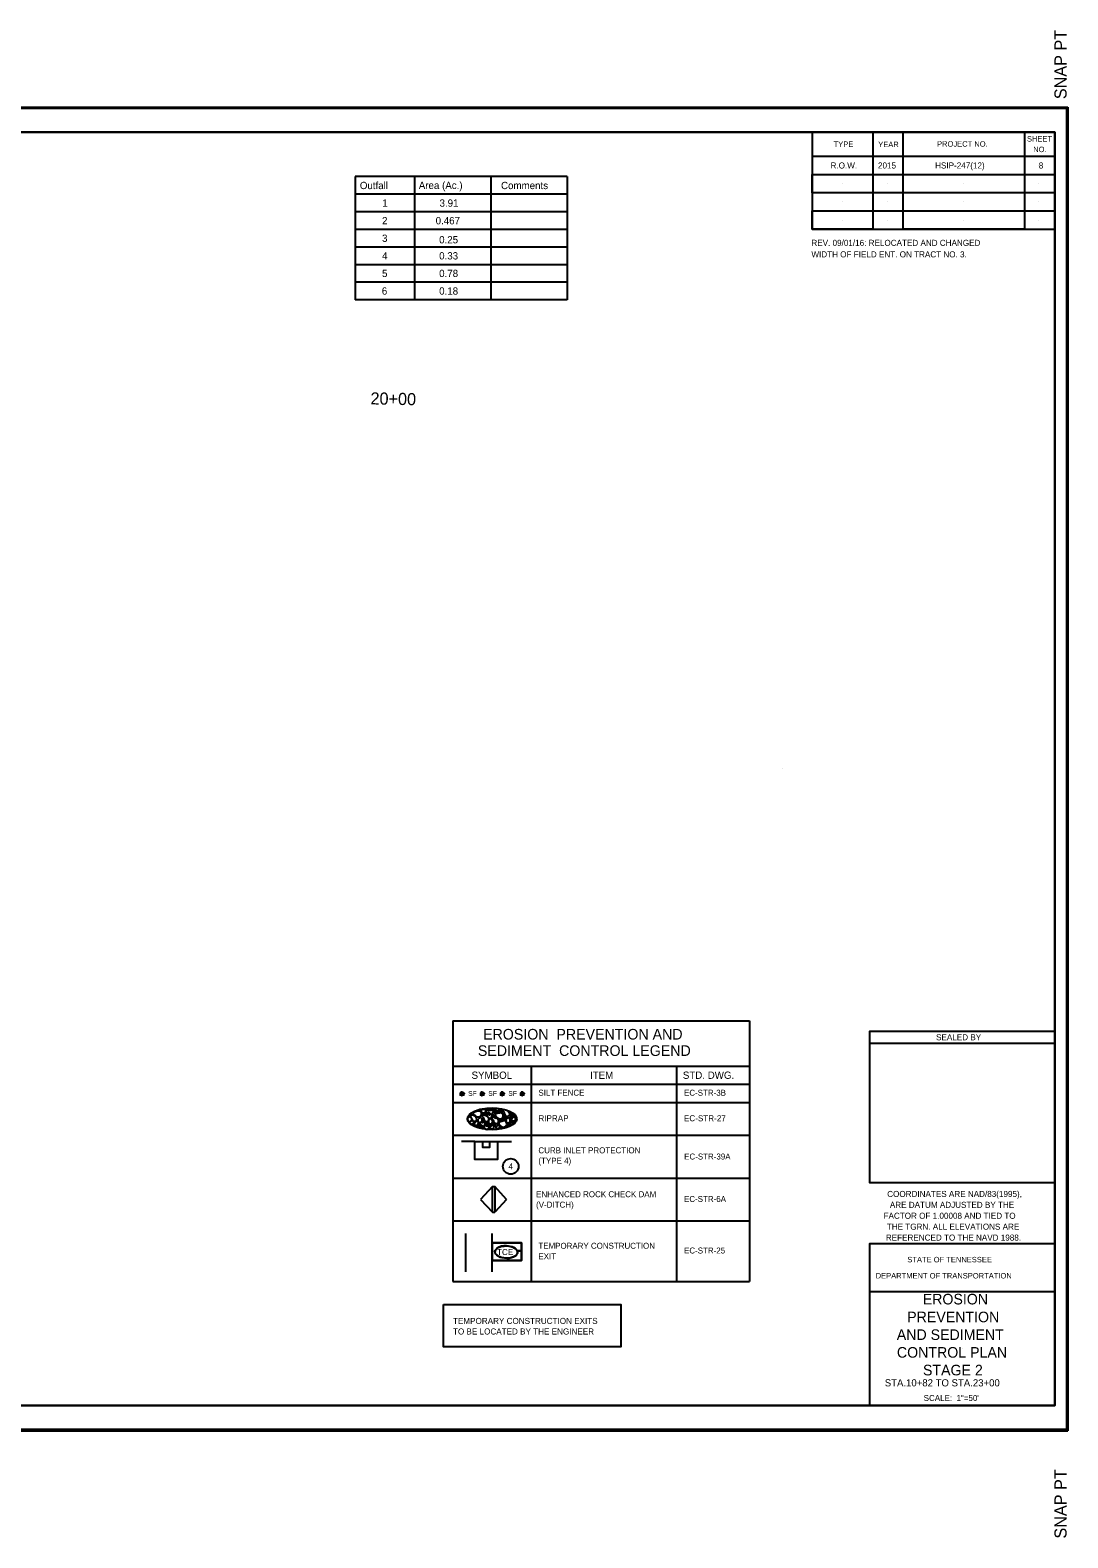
# Model space of a CAD drawing. Extents: x -200 to 1681714, y -325 to 518733.
# Drawn here: x 1680858 to 1681714, y 517490 to 518733 of the extents above; entities that cross this region are included whole.
import ezdxf

# ---------------------------------------------------------------- set-up
doc = ezdxf.new("R2010")
doc.units = 0
for name, color, linetype in [('DESIGN - CENTERLINE - Proposed Text', 7, 'Continuous'), ('DESIGN - EROSION CONTROL - Devices Text and Legends', 7, 'Continuous'), ('DESIGN - SCRATCH - User 1', 7, 'Continuous'), ('DESIGN - SHEET - Corner Text', 7, 'Continuous'), ('DESIGN - SHEET - Linework', 7, 'Continuous'), ('DESIGN - SHEET - Plot Shape', 7, 'Continuous'), ('DESIGN - TRANSPORTATION - Text', 7, 'Continuous')]:
    doc.layers.add(name, color=color, linetype=linetype)

msp = doc.modelspace()

# ---------------------------------------------------------------- linework, layer by layer
at = {"layer": 'DESIGN - EROSION CONTROL - Devices Text and Legends'}
for p, q in [((1681206.9, 517916.1), (1681206.9, 517863.9)), ((1681206.9, 517916.1), (1681451.4, 517916.1)), ((1681451.4, 517916.1), (1681451.4, 517863.9)), ((1681206.9, 517878.9), (1681451.4, 517878.9)), ((1681271.4, 517878.9), (1681271.4, 517863.9)), ((1681391.4, 517878.9), (1681391.4, 517863.9)), ((1681206.9, 517863.9), (1681451.4, 517863.9)), ((1681206.9, 517863.9), (1681206.9, 517848.8)), ((1681271.5, 517863.9), (1681271.5, 517848.8)), ((1681391.4, 517863.9), (1681391.4, 517848.8)), ((1681451.4, 517863.9), (1681451.4, 517848.8)), ((1681206.9, 517848.8), (1681206.9, 517822)), ((1681271.4, 517848.8), (1681271.4, 517822)), ((1681391.4, 517848.8), (1681391.4, 517822)), ((1681451.4, 517848.8), (1681451.4, 517822)), ((1681206.9, 517822), (1681206.9, 517786.6)), ((1681225, 517816.6), (1681214.1, 517816.6)), ((1681243.8, 517816.6), (1681255.2, 517816.6)), ((1681271.5, 517822), (1681271.5, 517786.6)), ((1681391.4, 517822), (1681391.4, 517786.6)), ((1681451.4, 517822), (1681451.4, 517786.6)), ((1681206.9, 517786.6), (1681206.9, 517751.2)), ((1681239.6, 517779.6), (1681229.8, 517769)), ((1681239.6, 517779.6), (1681241.4, 517779.6)), ((1681239.6, 517758.4), (1681239.6, 517779.6)), ((1681241.4, 517779.6), (1681241.4, 517758.4)), ((1681251.2, 517769), (1681241.4, 517779.6)), ((1681271.5, 517786.6), (1681271.5, 517751.2)), ((1681391.4, 517786.6), (1681391.4, 517751.2)), ((1681451.4, 517786.6), (1681451.4, 517751.2)), ((1681229.8, 517769), (1681239.6, 517758.4)), ((1681251.2, 517769), (1681241.4, 517758.4)), ((1681239.6, 517758.4), (1681241.4, 517758.4)), ((1681206.9, 517751.2), (1681206.9, 517701.4)), ((1681217.7, 517709.2), (1681217.7, 517741)), ((1681239.2, 517709.2), (1681239.2, 517741)), ((1681271.5, 517751.2), (1681271.5, 517701.4)), ((1681391.4, 517751.2), (1681391.4, 517701.4)), ((1681451.4, 517751.2), (1681451.4, 517701.4)), ((1681206.9, 517701.4), (1681451.4, 517701.4))]:
    msp.add_line(p, q, dxfattribs=at)
for points in [[(1681212.4, 517856.2), (1681216.4, 517856.2), (1681214.4, 517856.2), (1681214.4, 517854.3), (1681214.4, 517858.2)], [(1681213, 517857.6), (1681215.8, 517854.9), (1681214.4, 517856.2), (1681213, 517854.9), (1681215.8, 517857.6)], [(1681229, 517856.2), (1681232.9, 517856.2), (1681230.9, 517856.2), (1681230.9, 517854.3), (1681230.9, 517858.2)], [(1681229.6, 517857.6), (1681232.3, 517854.9), (1681230.9, 517856.2), (1681229.6, 517854.9), (1681232.3, 517857.6)], [(1681245.5, 517856.2), (1681249.4, 517856.2), (1681247.5, 517856.2), (1681247.5, 517854.3), (1681247.5, 517858.2)], [(1681246.1, 517857.6), (1681248.9, 517854.9), (1681247.5, 517856.2), (1681246.1, 517854.9), (1681248.9, 517857.6)], [(1681262, 517856.2), (1681266, 517856.2), (1681264, 517856.2), (1681264, 517854.3), (1681264, 517858.2)], [(1681262.6, 517857.6), (1681265.4, 517854.9), (1681264, 517856.2), (1681262.6, 517854.9), (1681265.4, 517857.6)], [(1681206.9, 517848.8), (1681451.4, 517848.8)], [(1681206.9, 517822), (1681451.4, 517822)], [(1681206.9, 517786.6), (1681451.4, 517786.6)], [(1681206.9, 517751.2), (1681451.4, 517751.2)], [(1681206.9, 517701.4), (1681451.4, 517701.4)]]:
    msp.add_lwpolyline(points, dxfattribs=at)
for points in [[(1681223.8, 517830.2), (1681227.7, 517830.2), (1681227.9, 517833.2), (1681225.4, 517832.9)], [(1681236.8, 517827.1), (1681240.7, 517827.1), (1681240.9, 517830.1), (1681238.4, 517829.8)], [(1681254.5, 517833.8), (1681258.5, 517833.8), (1681258.6, 517836.7), (1681256.1, 517836.5)], [(1681225, 517816.6), (1681243.8, 517816.6), (1681243.8, 517801.9), (1681225, 517801.9)], [(1681231.6, 517816.6), (1681237.2, 517816.6), (1681237.2, 517811.8), (1681231.6, 517811.8)], [(1681239.2, 517733.2), (1681263.6, 517733.2), (1681263.6, 517726.7), (1681260, 517726.7), (1681259.4, 517727.6), (1681258.5, 517728.4), (1681257.1, 517729.3), (1681255.7, 517729.9), (1681254.2, 517730.2), (1681252.8, 517730.5), (1681251, 517730.6), (1681249, 517730.6), (1681246.9, 517730.3), (1681244.7, 517729.6), (1681243.4, 517728.8), (1681242.2, 517727.7), (1681241.7, 517726.7), (1681241.5, 517725.7), (1681241.8, 517724.5), (1681242.5, 517723.6), (1681243.4, 517722.9), (1681244.7, 517722), (1681246, 517721.5), (1681247.4, 517721.1), (1681249.5, 517720.7), (1681249.5, 517720.7), (1681251.4, 517720.6), (1681253.2, 517720.6), (1681255.1, 517721), (1681257, 517721.6), (1681258.4, 517722.4), (1681258.7, 517722.6), (1681259.7, 517723.6), (1681260.3, 517724.8), (1681260.3, 517726), (1681260, 517726.7), (1681263.6, 517726.7), (1681263.6, 517718.5), (1681239.2, 517718.5)], [(1681239.2, 517718.5), (1681263.6, 517718.5), (1681263.6, 517733.2), (1681239.2, 517733.2)], [(1681199.2, 517682.2), (1681345.4, 517682.2), (1681345.4, 517647.4), (1681199.2, 517647.4)]]:
    msp.add_lwpolyline(points, close=True, dxfattribs=at)
msp.add_circle((1681254.6, 517796.2), 6.49, dxfattribs=at)
for centre, major_axis, ratio in [((1681239.2, 517835.4), (20.3, 0), 0.441611), ((1681250.9, 517725.6), (9.39, -0.3), 0.529481)]:
    msp.add_ellipse(centre, major_axis=major_axis, ratio=ratio, dxfattribs=at)
for points in [[(1681223.9, 517840.9), (1681223.9, 517839.5), (1681225.5, 517837.8), (1681227.1, 517836.9), (1681230.1, 517838.4), (1681229.3, 517841.9), (1681227.1, 517841.9), (1681223.9, 517840.9)], [(1681227.8, 517842.6), (1681228.5, 517841.9), (1681229.6, 517843.1), (1681227.9, 517842.6)], [(1681230.3, 517842.8), (1681231, 517840.3), (1681233.5, 517841), (1681233.5, 517843.2), (1681232, 517843.5), (1681230.3, 517842.8)], [(1681232.1, 517839.9), (1681231.4, 517839.1), (1681232.2, 517838.7), (1681232.9, 517839.5), (1681232, 517839.9)], [(1681233, 517839.1), (1681234.4, 517838), (1681234.9, 517837.7), (1681234.6, 517838.5), (1681235, 517838.8), (1681234.7, 517839.5), (1681234.3, 517839.9), (1681234.3, 517840.9), (1681234.1, 517841.3), (1681233.6, 517840.3), (1681233.1, 517839.1)], [(1681237.2, 517844.1), (1681234, 517842.8), (1681234.9, 517842.5), (1681236.9, 517842.7), (1681238.3, 517844.1), (1681237.2, 517844.1)], [(1681234.5, 517840.9), (1681234.6, 517839.5), (1681235.7, 517839.9), (1681234.9, 517840.8), (1681234.5, 517840.8)], [(1681234.9, 517838.2), (1681238.2, 517836.1), (1681239.4, 517839.3), (1681237.3, 517838.7), (1681236, 517839), (1681234.8, 517838.3)], [(1681235.6, 517841.6), (1681238.9, 517839.5), (1681240.1, 517842.7), (1681237.9, 517842.2), (1681236.6, 517842.5), (1681235.4, 517841.8)], [(1681236.4, 517840.4), (1681236.2, 517839.2), (1681237.3, 517838.8), (1681237.9, 517839.2), (1681237.1, 517840.3), (1681236.4, 517840.3)], [(1681238.8, 517844.2), (1681239, 517842.8), (1681240, 517843.2), (1681239.2, 517844.1), (1681238.8, 517844.2)], [(1681241.2, 517841.5), (1681240.6, 517840.7), (1681241.4, 517840.3), (1681242, 517841), (1681241.1, 517841.4)], [(1681240.7, 517844.1), (1681241.3, 517842), (1681241.7, 517841.2), (1681242.5, 517841.1), (1681243.6, 517841.6), (1681242.2, 517842.9), (1681240.7, 517844.1)], [(1681241.8, 517839.5), (1681242.1, 517837.9), (1681243.7, 517836.2), (1681245.3, 517835.2), (1681248.2, 517836.8), (1681247.4, 517840.2), (1681245.3, 517840.2), (1681241.6, 517839.5)], [(1681243.5, 517841.4), (1681242.5, 517840.9), (1681241.9, 517840.1), (1681242.5, 517839.9), (1681244.1, 517840.4), (1681244.7, 517840.8), (1681244, 517841.3), (1681243.6, 517841.3)], [(1681244.3, 517842.7), (1681244.2, 517841.5), (1681245.2, 517841), (1681245.9, 517841.5), (1681245, 517842.6), (1681244.3, 517842.7)], [(1681245.7, 517843.7), (1681245.8, 517842.2), (1681246.9, 517842.6), (1681246.1, 517843.5), (1681245.7, 517843.7)], [(1681246.7, 517842.1), (1681247.6, 517840.7), (1681248.4, 517840.8), (1681248.1, 517841.6), (1681246.7, 517842.1)], [(1681247.8, 517842.4), (1681249.2, 517840.3), (1681251.4, 517837.5), (1681253.4, 517838.1), (1681253.6, 517840.2), (1681251.1, 517842.4), (1681247.8, 517842.8)], [(1681254.5, 517840.8), (1681255, 517839), (1681255.4, 517838.2), (1681256.2, 517838.1), (1681257.3, 517838.6), (1681255.9, 517839.9), (1681254.5, 517841.1)], [(1681219, 517835.8), (1681219.7, 517833.3), (1681222.2, 517834), (1681222.2, 517836.2), (1681220.7, 517837.2), (1681219.3, 517836.1)], [(1681222.7, 517833.9), (1681220.7, 517832.4), (1681222.7, 517831.1), (1681224.2, 517832.4), (1681222.7, 517834)], [(1681220.7, 517838.2), (1681222.1, 517836.2), (1681224.4, 517833.4), (1681226.4, 517834), (1681226.5, 517836), (1681224, 517838.2), (1681220.7, 517838.7)], [(1681227.5, 517830), (1681227.4, 517828.9), (1681228.4, 517828.4), (1681229, 517828.8), (1681228.2, 517829.9), (1681227.5, 517830)], [(1681227.5, 517835.1), (1681228.2, 517832.6), (1681230.7, 517833.2), (1681230.7, 517835.5), (1681229.2, 517836.4), (1681227.8, 517835.4)], [(1681228.3, 517831.7), (1681228.4, 517830.2), (1681229.5, 517830.6), (1681228.7, 517831.5), (1681228.3, 517831.5)], [(1681229.1, 517831.7), (1681232.4, 517829.6), (1681233.6, 517832.8), (1681231.4, 517832.2), (1681230.1, 517832.5), (1681228.9, 517831.8)], [(1681229.3, 517830.4), (1681229.9, 517828.6), (1681230.3, 517827.8), (1681231.1, 517827.7), (1681232.1, 517828.2), (1681230.8, 517829.5), (1681229.3, 517830.7)], [(1681230.7, 517838), (1681232.1, 517835.9), (1681234.3, 517833.1), (1681236.3, 517833.7), (1681236.5, 517835.8), (1681234, 517838), (1681230.7, 517838.4)], [(1681231.7, 517835.7), (1681231, 517834.9), (1681231.8, 517834.5), (1681232.5, 517835.3), (1681231.6, 517835.7)], [(1681232.2, 517833.9), (1681231.6, 517833.2), (1681232.4, 517832.8), (1681233, 517833.5), (1681232.1, 517833.9)], [(1681232.4, 517828.9), (1681235.7, 517826.8), (1681236.9, 517830), (1681234.7, 517829.4), (1681233.4, 517829.7), (1681232.2, 517829)], [(1681234, 517832.6), (1681234.5, 517830.7), (1681234.9, 517830), (1681235.7, 517829.8), (1681236.8, 517830.4), (1681235.4, 517831.7), (1681234, 517832.9)], [(1681236.2, 517833.9), (1681236.9, 517831.4), (1681239.4, 517832.1), (1681239.4, 517834.4), (1681237.9, 517835.3), (1681236.5, 517834.2)], [(1681238.7, 517831.7), (1681238.5, 517830.5), (1681239.6, 517830), (1681240.2, 517830.4), (1681239.4, 517831.5), (1681238.7, 517831.6)], [(1681238.6, 517836.4), (1681240, 517834.4), (1681242.3, 517831.5), (1681244.3, 517832.2), (1681244.4, 517834.2), (1681241.9, 517836.4), (1681238.6, 517836.9)], [(1681240.1, 517838.7), (1681240.2, 517837.2), (1681241.3, 517837.6), (1681240.5, 517838.6), (1681240.1, 517838.6)], [(1681240.4, 517831.9), (1681240.7, 517830.2), (1681241.4, 517829.7), (1681242, 517830.3), (1681242.4, 517831), (1681241, 517831.8), (1681240.4, 517832)], [(1681241.3, 517837.7), (1681241.1, 517836.5), (1681242.2, 517836.1), (1681242.8, 517836.5), (1681242, 517837.6), (1681241.3, 517837.6)], [(1681244.2, 517830.4), (1681242.3, 517827.9), (1681244.2, 517827.5), (1681245.7, 517828.8), (1681244.1, 517830.4)], [(1681244.6, 517832.7), (1681244.9, 517831.1), (1681246.5, 517829.4), (1681248.1, 517828.5), (1681251.1, 517830), (1681250.2, 517833.5), (1681248.1, 517833.5), (1681244.6, 517832.5)], [(1681245.6, 517835.2), (1681244.9, 517834.4), (1681245.7, 517834), (1681246.4, 517834.8), (1681245.5, 517835.2)], [(1681248.7, 517835.6), (1681245.6, 517834.3), (1681246.4, 517833.9), (1681248.5, 517834.2), (1681249.8, 517835.5), (1681248.7, 517835.6)], [(1681246.3, 517828.6), (1681245.6, 517827.8), (1681246.4, 517827.4), (1681247.1, 517828.1), (1681246.2, 517828.5)], [(1681249.1, 517838), (1681249.2, 517836.6), (1681250.1, 517836.3), (1681250.6, 517837.3), (1681250.9, 517837.8), (1681250.1, 517838.1), (1681248.9, 517838.1)], [(1681250.2, 517836.4), (1681250.9, 517835.6), (1681252.1, 517836.8), (1681250.4, 517836.4)], [(1681250.7, 517834.8), (1681251.3, 517832.3), (1681253.8, 517833), (1681253.8, 517835.2), (1681252.4, 517836.2), (1681250.9, 517835.1)], [(1681251.7, 517830), (1681252.6, 517829.1), (1681252.7, 517828.9), (1681252.8, 517829.5), (1681253.2, 517829.9), (1681252.9, 517830.5), (1681252.5, 517831), (1681253.1, 517831.5), (1681252.8, 517831.9), (1681251.8, 517831.4), (1681251.7, 517830.2)], [(1681253.5, 517832.1), (1681253.6, 517830.7), (1681254.7, 517831.1), (1681253.9, 517832), (1681253.5, 517832)], [(1681254.1, 517839.1), (1681253.4, 517838.3), (1681254.3, 517837.9), (1681254.9, 517838.6), (1681254, 517839.1)], [(1681254, 517837.1), (1681254.1, 517835.8), (1681254.9, 517835.4), (1681255.5, 517836.4), (1681255.8, 517837), (1681255, 517837.3), (1681253.8, 517837.2)], [(1681254.4, 517833.7), (1681254.3, 517832.6), (1681255.3, 517832.1), (1681255.9, 517832.5), (1681255.1, 517833.6), (1681254.4, 517833.7)], [(1681256.3, 517833.4), (1681256.4, 517831.9), (1681257.5, 517832.3), (1681256.7, 517833.2), (1681256.3, 517833.2)], [(1681257.5, 517838.3), (1681256.9, 517837.5), (1681257.7, 517837.1), (1681258.3, 517837.8), (1681257.4, 517838.2)]]:
    msp.add_spline(points, degree=3, dxfattribs=at)
at = {"layer": 'DESIGN - SCRATCH - User 1'}
for p, q in [((1681528.1, 518621.5), (1681528.1, 518621.5)), ((1681565.1, 518621.5), (1681565.1, 518621.5)), ((1681627.6, 518621.5), (1681627.6, 518621.5)), ((1681690.1, 518621.5), (1681690.1, 518621.5)), ((1681528.1, 518606.5), (1681528.1, 518606.5)), ((1681565.1, 518606.5), (1681565.1, 518606.5)), ((1681627.6, 518606.5), (1681627.6, 518606.5)), ((1681690.1, 518606.5), (1681690.1, 518606.5)), ((1681528.1, 518591.5), (1681528.1, 518591.5)), ((1681565.1, 518591.5), (1681565.1, 518591.5)), ((1681627.6, 518591.5), (1681627.6, 518591.5)), ((1681690.1, 518591.5), (1681690.1, 518591.5)), ((1681528.1, 518576.5), (1681528.1, 518576.5)), ((1681565.1, 518576.5), (1681565.1, 518576.5)), ((1681627.6, 518576.5), (1681627.6, 518576.5)), ((1681690.1, 518576.5), (1681690.1, 518576.5)), ((1681478.9, 518124), (1681478.9, 518124)), ((1681626.8, 517645.8), (1681626.8, 517645.8))]:
    msp.add_line(p, q, dxfattribs=at)
at = {"layer": 'DESIGN - SHEET - Linework'}
for p, q in [((1680011.9, 518669.7), (1681713.9, 518669.7)), ((1681713.9, 518669.7), (1681713.9, 517578.3)), ((1681550.6, 517897.7), (1681703.1, 517897.7)), ((1680011.9, 517578.3), (1681713.9, 517578.3))]:
    msp.add_line(p, q, dxfattribs=at)
for points in [[(1680128.9, 518649), (1680128.9, 517599), (1681703.1, 517599), (1681703.1, 518649), (1680128.9, 518649)], [(1681503.1, 518649), (1681503.1, 518569), (1681703.1, 518569), (1681703.1, 518649), (1681678.1, 518649), (1681678.1, 518569), (1681578.1, 518569), (1681578.1, 518649), (1681553.1, 518649), (1681553.1, 518569), (1681503.1, 518569), (1681503.1, 518584), (1681703.1, 518584), (1681703.1, 518599), (1681503.1, 518599), (1681503.1, 518614), (1681703.1, 518614), (1681703.1, 518629), (1681503.1, 518629)], [(1681550.6, 517599), (1681550.6, 517732.7), (1681703.1, 517732.7), (1681703.1, 517692.7), (1681550.6, 517692.7)]]:
    msp.add_lwpolyline(points, dxfattribs=at)
msp.add_lwpolyline([(1681703.1, 517782.7), (1681550.6, 517782.7), (1681550.6, 517907.7), (1681703.1, 517907.7)], close=True, dxfattribs=at)
at = {"layer": 'DESIGN - SHEET - Plot Shape'}
for points in [[(1680012.9, 518668.7), (1681712.9, 518668.7), (1681712.9, 517579.3), (1680012.9, 517579.3)], [(1680043.8, 518649), (1681703.1, 518649), (1681703.1, 517599), (1680043.8, 517599)]]:
    msp.add_lwpolyline(points, close=True, dxfattribs=at)
at = {"layer": 'DESIGN - TRANSPORTATION - Text'}
for p, q in [((1681301, 518612.3), (1681126.2, 518612.3)), ((1681126.2, 518612.3), (1681126.2, 518510.7)), ((1681175.2, 518612.3), (1681175.2, 518510.7)), ((1681238.1, 518612.3), (1681238.1, 518510.7)), ((1681301, 518612.3), (1681301, 518510.7)), ((1681301, 518597.7), (1681126.2, 518597.8)), ((1681301, 518583.2), (1681126.2, 518583.3)), ((1681301, 518568.7), (1681126.2, 518568.8)), ((1681301, 518554.2), (1681126.2, 518554.2)), ((1681301, 518539.7), (1681126.2, 518539.7)), ((1681301, 518525.2), (1681126.2, 518525.2)), ((1681301, 518510.7), (1681126.2, 518510.7))]:
    msp.add_line(p, q, dxfattribs=at)

# ---------------------------------------------------------------- texts
at = {"layer": 'DESIGN - CENTERLINE - Proposed Text'}
msp.add_text('20+00', height=10, rotation=358.8704, dxfattribs=at).set_placement((1681138.9, 518424.5))
at = {"layer": 'DESIGN - EROSION CONTROL - Devices Text and Legends'}
for s, height, p in [('EROSION  PREVENTION AND', 8.75, (1681231.8, 517900.8)), ('SEDIMENT  CONTROL LEGEND', 8.75, (1681227.5, 517887.3)), ('SYMBOL', 6, (1681222.3, 517868.4)), ('ITEM', 6, (1681320, 517868.4)), ('STD. DWG.', 6, (1681396.5, 517868.4)), ('SF', 4, (1681219.5, 517854.3)), ('SF', 4, (1681236.1, 517854.3)), ('SF', 4, (1681252.6, 517854.3)), ('SILT FENCE', 4.92, (1681277.4, 517854.5)), ('EC-STR-3B', 4.9, (1681397.5, 517854.5)), ('RIPRAP', 5, (1681277.4, 517833.4)), ('EC-STR-27', 5, (1681397.4, 517833.4)), ('CURB INLET PROTECTION', 4.921, (1681277.4, 517807)), ('(TYPE 4)', 4.92, (1681277.4, 517798.4)), ('EC-STR-39A', 4.9, (1681397.6, 517801.9)), ('(V-DITCH)', 4.92, (1681275.5, 517762.2)), ('ENHANCED ROCK CHECK DAM ', 4.921, (1681275.5, 517770.8)), ('EC-STR-6A', 4.9, (1681397.5, 517766.9)), ('TCE', 5, (1681243.3, 517723.1)), ('TEMPORARY CONSTRUCTION', 4.9, (1681277.4, 517728.3)), ('EC-STR-25', 4.9, (1681397.5, 517724.4)), ('EXIT', 4.9, (1681277.4, 517719.6)), ('TEMPORARY CONSTRUCTION EXITS', 5, (1681207, 517666.3)), ('TO BE LOCATED BY THE ENGINEER', 5, (1681207, 517657.6))]:
    msp.add_text(s, height=height, dxfattribs=at).set_placement(p)
msp.add_text('4', height=5, rotation=359.7818, dxfattribs=at).set_placement((1681252.7, 517793.7))
at = {"layer": 'DESIGN - SHEET - Corner Text'}
for s, height, rotation, p in [('  SNAP PT', 10, 90, (1681712.9, 518668.7)), ('REV. 09/01/16: RELOCATED AND CHANGED', 5, 360, (1681502.5, 518555.2)), ('WIDTH OF FIELD ENT. ON TRACT NO. 3.', 5, 360, (1681502.5, 518545.7)), ('SEALED BY', 5, 360, (1681605.3, 517900.2)), ('SNAP PT  ', 10, 90, (1681712.9, 517489.3))]:
    msp.add_text(s, height=height, rotation=rotation, dxfattribs=at).set_placement(p)
for s, height, p in [('NO.', 4.5, (1681685.4, 518632.5)), ('R.O.W.', 5, (1681518.3, 518619)), ('2015', 5, (1681557.4, 518619)), ('HSIP-247(12)', 5, (1681604.5, 518619)), ('8', 5, (1681690, 518619)), ('COORDINATES ARE NAD/83(1995),', 5, (1681565, 517771)), ('ARE DATUM ADJUSTED BY THE', 5, (1681567.2, 517762)), ('FACTOR OF 1.00008 AND TIED TO', 5, (1681562, 517753)), ('REFERENCED TO THE NAVD 1988.', 5, (1681563.9, 517735)), ('THE TGRN. ALL ELEVATIONS ARE', 5, (1681564.7, 517744)), ('STATE OF TENNESSEE', 4.5, (1681581.6, 517717.1)), ('DEPARTMENT OF TRANSPORTATION', 4.5, (1681555.5, 517703.8)), ('EROSION', 8.73, (1681594.3, 517682.4)), ('PREVENTION', 8.73, (1681581.5, 517667.7)), ('AND SEDIMENT', 8.734, (1681572.9, 517653.1)), ('CONTROL PLAN', 8.734, (1681573, 517638.5)), ('STAGE 2', 8.73, (1681594.5, 517623.9)), ('STA.10+82 TO STA.23+00', 5.905, (1681563, 517614.8)), ('SCALE:  1"=50\'', 4.921, (1681595.1, 517602.8))]:
    msp.add_text(s, height=height, dxfattribs=at).set_placement(p)
at = {"layer": 'DESIGN - SHEET - Linework'}
for s, p in [('TYPE', (1681520.8, 518636.8)), ('YEAR', (1681557.6, 518636.6)), ('PROJECT NO.', (1681606.1, 518637)), ('SHEET', (1681680.2, 518641.2)), ('NO.', (1681685.4, 518632.5))]:
    msp.add_text(s, height=4.5, dxfattribs=at).set_placement(p)
at = {"layer": 'DESIGN - TRANSPORTATION - Text'}
for s, p in [('Outfall', (1681130.2, 518602)), ('Area (Ac.)', (1681178.8, 518602.1)), ('Comments', (1681246.6, 518602)), ('1', (1681148.7, 518587.5)), ('3.91', (1681195.9, 518587.5)), ('2', (1681148.5, 518573)), ('0.467', (1681192.7, 518573)), ('3', (1681148.5, 518558.5)), ('0.25', (1681195.6, 518557.3)), ('4', (1681148.5, 518544)), ('0.33', (1681195.6, 518544)), ('5', (1681148.5, 518529.5)), ('0.78', (1681195.6, 518529.5)), ('6', (1681148.3, 518515)), ('0.18', (1681195.6, 518515))]:
    msp.add_text(s, height=6, rotation=359.9877, dxfattribs=at).set_placement(p)

doc.saveas('drawing.dxf')
